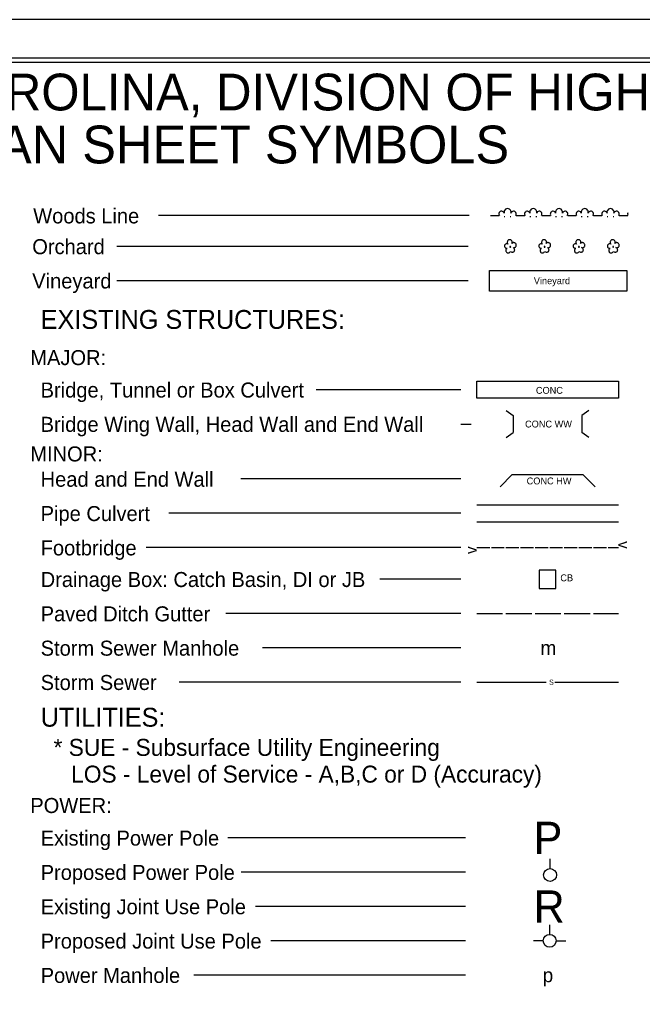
# Model space of a CAD drawing. Extents: x 2041685 to 2043369, y 619046 to 620146.
# Drawn here: x 2042608 to 2042971, y 619576 to 620146 of the extents above; entities that cross this region are included whole.
import ezdxf

# ---------------------------------------------------------------- set-up
doc = ezdxf.new("R2010")
doc.units = 0
for name, color, linetype in [('Sheet Cutting Line CELL', 7, 'Continuous'), ('Sheet Plot Border Inside CELL', 7, 'Continuous'), ('Sheet Plot Border Outside CELL', 7, 'Continuous'), ('Sheet Symbology CELL', 7, 'Continuous')]:
    doc.layers.add(name, color=color, linetype=linetype)

msp = doc.modelspace()

# ---------------------------------------------------------------- linework, layer by layer
at = {"layer": 'Sheet Cutting Line CELL'}
msp.add_line((2043369.03, 620145.62), (2041685.03, 620145.62), dxfattribs=at)
at = {"layer": 'Sheet Plot Border Inside CELL'}
msp.add_lwpolyline([(2041698.03, 619068.07), (2043364.53, 619068.07), (2043364.53, 620123.17), (2041698.03, 620123.17)], close=True, dxfattribs=at)
at = {"layer": 'Sheet Plot Border Outside CELL'}
msp.add_lwpolyline([(2041685.03, 619045.62), (2043369.03, 619045.62), (2043369.03, 620145.62), (2041685.03, 620145.62)], close=True, dxfattribs=at)
at = {"layer": 'Sheet Symbology CELL'}
for p, q in [((2042870.29, 620031.35), (2042689.16, 620031.35)), ((2042882.68, 620031.35), (2042887.68, 620031.35)), ((2042890.63, 620030.85), (2042891.13, 620030.85)), ((2042894.13, 620030.85), (2042894.63, 620030.85)), ((2042897.68, 620031.35), (2042902.68, 620031.35)), ((2042905.63, 620030.85), (2042906.13, 620030.85)), ((2042909.13, 620030.85), (2042909.63, 620030.85)), ((2042912.68, 620031.35), (2042917.68, 620031.35)), ((2042920.63, 620030.85), (2042921.13, 620030.85)), ((2042924.13, 620030.85), (2042924.63, 620030.85)), ((2042927.68, 620031.35), (2042932.68, 620031.35)), ((2042935.63, 620030.85), (2042936.13, 620030.85)), ((2042939.13, 620030.85), (2042939.63, 620030.85)), ((2042942.68, 620031.35), (2042947.68, 620031.35)), ((2042950.63, 620030.85), (2042951.13, 620030.85)), ((2042954.13, 620030.85), (2042954.63, 620030.85)), ((2042957.68, 620031.35), (2042962.68, 620031.35)), ((2042869.72, 620013.42), (2042664.79, 620013.42)), ((2042869.72, 619993.42), (2042664.79, 619993.42)), ((2042865.41, 619929.92), (2042780.98, 619929.92)), ((2042891.86, 619917.78), (2042895.96, 619914.92)), ((2042895.96, 619914.92), (2042895.96, 619904.92)), ((2042940.06, 619917.78), (2042935.96, 619914.92)), ((2042935.96, 619914.92), (2042935.96, 619904.92)), ((2042865.41, 619909.92), (2042871.4, 619909.92)), ((2042891.86, 619902.05), (2042895.96, 619904.92)), ((2042940.06, 619902.05), (2042935.96, 619904.92)), ((2042888.26, 619873.35), (2042895.33, 619880.42)), ((2042895.33, 619880.42), (2042936.58, 619880.42)), ((2042936.58, 619880.42), (2042943.66, 619873.35)), ((2042865.41, 619877.92), (2042737.11, 619877.92)), ((2042874.71, 619862.92), (2042957.21, 619862.92)), ((2042865.41, 619857.92), (2042695.22, 619857.92)), ((2042874.71, 619852.92), (2042957.21, 619852.92)), ((2042865.41, 619837.92), (2042681.93, 619837.92)), ((2042874.71, 619837.92), (2042882.21, 619837.92)), ((2042883.21, 619837.92), (2042890.71, 619837.92)), ((2042891.71, 619837.92), (2042899.21, 619837.92)), ((2042900.21, 619837.92), (2042907.71, 619837.92)), ((2042908.71, 619837.92), (2042916.21, 619837.92)), ((2042917.21, 619837.92), (2042924.71, 619837.92)), ((2042925.71, 619837.92), (2042933.21, 619837.92)), ((2042934.21, 619837.92), (2042941.71, 619837.92)), ((2042942.71, 619837.92), (2042950.21, 619837.92)), ((2042951.21, 619837.92), (2042957.21, 619837.92)), ((2042865.41, 619819.49), (2042818.21, 619819.49)), ((2042865.41, 619799.49), (2042728.46, 619799.49)), ((2042874.71, 619799.49), (2042889.71, 619799.49)), ((2042891.71, 619799.49), (2042906.71, 619799.49)), ((2042908.71, 619799.49), (2042923.71, 619799.49)), ((2042925.71, 619799.49), (2042940.71, 619799.49)), ((2042942.71, 619799.49), (2042957.21, 619799.49)), ((2042865.41, 619779.49), (2042749.73, 619779.49)), ((2042865.41, 619759.49), (2042701.21, 619759.49)), ((2042874.71, 619759.49), (2042915.23, 619759.49)), ((2042920.23, 619759.49), (2042957.21, 619759.49)), ((2042868.2, 619668.8), (2042729.5, 619668.8)), ((2042917.42, 619650.92), (2042917.42, 619656.54)), ((2042868.2, 619648.8), (2042737.28, 619648.8)), ((2042868.2, 619628.8), (2042745.68, 619628.8)), ((2042917.21, 619612.57), (2042917.21, 619618.19)), ((2042868.2, 619608.8), (2042754.68, 619608.8)), ((2042913.46, 619608.82), (2042907.83, 619608.82)), ((2042920.96, 619608.82), (2042926.58, 619608.82)), ((2042868.2, 619588.8), (2042709.7, 619588.8))]:
    msp.add_line(p, q, dxfattribs=at)
for points in [[(2043352.03, 620120.62), (2041852.03, 620120.62), (2041852.03, 619071.63), (2043352.03, 619071.63)], [(2042911.15, 619814.17), (2042920.76, 619814.17), (2042920.76, 619824.81), (2042911.15, 619824.81)]]:
    msp.add_lwpolyline(points, close=True, dxfattribs=at)
for points in [[(2042895.17, 620015.17), (2042895.32, 620015.47), (2042895.37, 620015.77), (2042895.32, 620016.07), (2042895.27, 620016.37), (2042895.12, 620016.62), (2042894.97, 620016.87), (2042894.72, 620017.07), (2042894.47, 620017.22), (2042894.12, 620017.32), (2042893.87, 620017.32), (2042893.57, 620017.27), (2042893.27, 620017.17), (2042893.02, 620017.02), (2042892.77, 620016.82), (2042892.62, 620016.52), (2042892.52, 620016.27), (2042892.47, 620015.97), (2042892.47, 620015.67), (2042892.52, 620015.37), (2042892.67, 620015.12), (2042892.87, 620014.82), (2042892.62, 620014.97), (2042892.32, 620015.02), (2042892.02, 620015.02), (2042891.77, 620014.92), (2042891.52, 620014.82), (2042891.27, 620014.62), (2042891.07, 620014.42), (2042890.92, 620014.17), (2042890.87, 620013.92), (2042890.82, 620013.57), (2042890.87, 620013.32), (2042890.97, 620013.07), (2042891.17, 620012.82), (2042891.32, 620012.62), (2042891.57, 620012.47), (2042891.87, 620012.32), (2042892.12, 620012.27), (2042892.42, 620012.27), (2042892.17, 620012.17), (2042891.92, 620011.97), (2042891.77, 620011.77), (2042891.67, 620011.47), (2042891.57, 620011.17), (2042891.57, 620010.92), (2042891.62, 620010.62), (2042891.77, 620010.37), (2042891.92, 620010.12), (2042892.12, 620009.92), (2042892.37, 620009.77), (2042892.62, 620009.67), (2042892.92, 620009.67), (2042893.22, 620009.67), (2042893.47, 620009.72), (2042893.72, 620009.92), (2042893.97, 620010.07), (2042894.22, 620010.52)], [(2042894.22, 620010.52), (2042894.82, 620010.17), (2042895.12, 620010.07), (2042895.42, 620010.02), (2042895.72, 620010.07), (2042895.97, 620010.17), (2042896.22, 620010.32), (2042896.47, 620010.52), (2042896.62, 620010.77), (2042896.72, 620011.02), (2042896.82, 620011.32), (2042896.77, 620011.62), (2042896.72, 620011.92), (2042896.52, 620012.22), (2042896.37, 620012.42), (2042896.12, 620012.57), (2042895.82, 620012.72), (2042896.12, 620012.67), (2042896.47, 620012.67), (2042896.72, 620012.77), (2042897.02, 620012.92), (2042897.27, 620013.07), (2042897.47, 620013.32), (2042897.62, 620013.62), (2042897.67, 620013.92), (2042897.72, 620014.22), (2042897.67, 620014.52), (2042897.57, 620014.82), (2042897.37, 620015.07), (2042897.12, 620015.32), (2042896.87, 620015.47), (2042896.57, 620015.57), (2042896.27, 620015.62), (2042895.97, 620015.62), (2042895.67, 620015.52), (2042895.42, 620015.37), (2042895.17, 620015.17)], [(2042915.17, 620015.17), (2042915.32, 620015.47), (2042915.37, 620015.77), (2042915.32, 620016.07), (2042915.27, 620016.37), (2042915.12, 620016.62), (2042914.97, 620016.87), (2042914.72, 620017.07), (2042914.47, 620017.22), (2042914.12, 620017.32), (2042913.87, 620017.32), (2042913.57, 620017.27), (2042913.27, 620017.17), (2042913.02, 620017.02), (2042912.77, 620016.82), (2042912.62, 620016.52), (2042912.52, 620016.27), (2042912.47, 620015.97), (2042912.47, 620015.67), (2042912.52, 620015.37), (2042912.67, 620015.12), (2042912.87, 620014.82), (2042912.62, 620014.97), (2042912.32, 620015.02), (2042912.02, 620015.02), (2042911.77, 620014.92), (2042911.52, 620014.82), (2042911.27, 620014.62), (2042911.07, 620014.42), (2042910.92, 620014.17), (2042910.87, 620013.92), (2042910.82, 620013.57), (2042910.87, 620013.32), (2042910.97, 620013.07), (2042911.17, 620012.82), (2042911.32, 620012.62), (2042911.57, 620012.47), (2042911.87, 620012.32), (2042912.12, 620012.27), (2042912.42, 620012.27), (2042912.17, 620012.17), (2042911.92, 620011.97), (2042911.77, 620011.77), (2042911.67, 620011.47), (2042911.57, 620011.17), (2042911.57, 620010.92), (2042911.62, 620010.62), (2042911.77, 620010.37), (2042911.92, 620010.12), (2042912.12, 620009.92), (2042912.37, 620009.77), (2042912.62, 620009.67), (2042912.92, 620009.67), (2042913.22, 620009.67), (2042913.47, 620009.72), (2042913.72, 620009.92), (2042913.97, 620010.07), (2042914.22, 620010.52)], [(2042914.22, 620010.52), (2042914.82, 620010.17), (2042915.12, 620010.07), (2042915.42, 620010.02), (2042915.72, 620010.07), (2042915.97, 620010.17), (2042916.22, 620010.32), (2042916.47, 620010.52), (2042916.62, 620010.77), (2042916.72, 620011.02), (2042916.82, 620011.32), (2042916.77, 620011.62), (2042916.72, 620011.92), (2042916.52, 620012.22), (2042916.37, 620012.42), (2042916.12, 620012.57), (2042915.82, 620012.72), (2042916.12, 620012.67), (2042916.47, 620012.67), (2042916.72, 620012.77), (2042917.02, 620012.92), (2042917.27, 620013.07), (2042917.47, 620013.32), (2042917.62, 620013.62), (2042917.67, 620013.92), (2042917.72, 620014.22), (2042917.67, 620014.52), (2042917.57, 620014.82), (2042917.37, 620015.07), (2042917.12, 620015.32), (2042916.87, 620015.47), (2042916.57, 620015.57), (2042916.27, 620015.62), (2042915.97, 620015.62), (2042915.67, 620015.52), (2042915.42, 620015.37), (2042915.17, 620015.17)], [(2042935.17, 620015.17), (2042935.32, 620015.47), (2042935.37, 620015.77), (2042935.32, 620016.07), (2042935.27, 620016.37), (2042935.12, 620016.62), (2042934.97, 620016.87), (2042934.72, 620017.07), (2042934.47, 620017.22), (2042934.12, 620017.32), (2042933.87, 620017.32), (2042933.57, 620017.27), (2042933.27, 620017.17), (2042933.02, 620017.02), (2042932.77, 620016.82), (2042932.62, 620016.52), (2042932.52, 620016.27), (2042932.47, 620015.97), (2042932.47, 620015.67), (2042932.52, 620015.37), (2042932.67, 620015.12), (2042932.87, 620014.82), (2042932.62, 620014.97), (2042932.32, 620015.02), (2042932.02, 620015.02), (2042931.77, 620014.92), (2042931.52, 620014.82), (2042931.27, 620014.62), (2042931.07, 620014.42), (2042930.92, 620014.17), (2042930.87, 620013.92), (2042930.82, 620013.57), (2042930.87, 620013.32), (2042930.97, 620013.07), (2042931.17, 620012.82), (2042931.32, 620012.62), (2042931.57, 620012.47), (2042931.87, 620012.32), (2042932.12, 620012.27), (2042932.42, 620012.27), (2042932.17, 620012.17), (2042931.92, 620011.97), (2042931.77, 620011.77), (2042931.67, 620011.47), (2042931.57, 620011.17), (2042931.57, 620010.92), (2042931.62, 620010.62), (2042931.77, 620010.37), (2042931.92, 620010.12), (2042932.12, 620009.92), (2042932.37, 620009.77), (2042932.62, 620009.67), (2042932.92, 620009.67), (2042933.22, 620009.67), (2042933.47, 620009.72), (2042933.72, 620009.92), (2042933.97, 620010.07), (2042934.22, 620010.52)], [(2042934.22, 620010.52), (2042934.82, 620010.17), (2042935.12, 620010.07), (2042935.42, 620010.02), (2042935.72, 620010.07), (2042935.97, 620010.17), (2042936.22, 620010.32), (2042936.47, 620010.52), (2042936.62, 620010.77), (2042936.72, 620011.02), (2042936.82, 620011.32), (2042936.77, 620011.62), (2042936.72, 620011.92), (2042936.52, 620012.22), (2042936.37, 620012.42), (2042936.12, 620012.57), (2042935.82, 620012.72), (2042936.12, 620012.67), (2042936.47, 620012.67), (2042936.72, 620012.77), (2042937.02, 620012.92), (2042937.27, 620013.07), (2042937.47, 620013.32), (2042937.62, 620013.62), (2042937.67, 620013.92), (2042937.72, 620014.22), (2042937.67, 620014.52), (2042937.57, 620014.82), (2042937.37, 620015.07), (2042937.12, 620015.32), (2042936.87, 620015.47), (2042936.57, 620015.57), (2042936.27, 620015.62), (2042935.97, 620015.62), (2042935.67, 620015.52), (2042935.42, 620015.37), (2042935.17, 620015.17)], [(2042955.17, 620015.17), (2042955.32, 620015.47), (2042955.37, 620015.77), (2042955.32, 620016.07), (2042955.27, 620016.37), (2042955.12, 620016.62), (2042954.97, 620016.87), (2042954.72, 620017.07), (2042954.47, 620017.22), (2042954.12, 620017.32), (2042953.87, 620017.32), (2042953.57, 620017.27), (2042953.27, 620017.17), (2042953.02, 620017.02), (2042952.77, 620016.82), (2042952.62, 620016.52), (2042952.52, 620016.27), (2042952.47, 620015.97), (2042952.47, 620015.67), (2042952.52, 620015.37), (2042952.67, 620015.12), (2042952.87, 620014.82), (2042952.62, 620014.97), (2042952.32, 620015.02), (2042952.02, 620015.02), (2042951.77, 620014.92), (2042951.52, 620014.82), (2042951.27, 620014.62), (2042951.07, 620014.42), (2042950.92, 620014.17), (2042950.87, 620013.92), (2042950.82, 620013.57), (2042950.87, 620013.32), (2042950.97, 620013.07), (2042951.17, 620012.82), (2042951.32, 620012.62), (2042951.57, 620012.47), (2042951.87, 620012.32), (2042952.12, 620012.27), (2042952.42, 620012.27), (2042952.17, 620012.17), (2042951.92, 620011.97), (2042951.77, 620011.77), (2042951.67, 620011.47), (2042951.57, 620011.17), (2042951.57, 620010.92), (2042951.62, 620010.62), (2042951.77, 620010.37), (2042951.92, 620010.12), (2042952.12, 620009.92), (2042952.37, 620009.77), (2042952.62, 620009.67), (2042952.92, 620009.67), (2042953.22, 620009.67), (2042953.47, 620009.72), (2042953.72, 620009.92), (2042953.97, 620010.07), (2042954.22, 620010.52)], [(2042954.22, 620010.52), (2042954.82, 620010.17), (2042955.12, 620010.07), (2042955.42, 620010.02), (2042955.72, 620010.07), (2042955.97, 620010.17), (2042956.22, 620010.32), (2042956.47, 620010.52), (2042956.62, 620010.77), (2042956.72, 620011.02), (2042956.82, 620011.32), (2042956.77, 620011.62), (2042956.72, 620011.92), (2042956.52, 620012.22), (2042956.37, 620012.42), (2042956.12, 620012.57), (2042955.82, 620012.72), (2042956.12, 620012.67), (2042956.47, 620012.67), (2042956.72, 620012.77), (2042957.02, 620012.92), (2042957.27, 620013.07), (2042957.47, 620013.32), (2042957.62, 620013.62), (2042957.67, 620013.92), (2042957.72, 620014.22), (2042957.67, 620014.52), (2042957.57, 620014.82), (2042957.37, 620015.07), (2042957.12, 620015.32), (2042956.87, 620015.47), (2042956.57, 620015.57), (2042956.27, 620015.62), (2042955.97, 620015.62), (2042955.67, 620015.52), (2042955.42, 620015.37), (2042955.17, 620015.17)], [(2042894.32, 620013.42), (2042894.17, 620013.42), (2042894.07, 620013.37), (2042893.97, 620013.32), (2042893.97, 620013.17), (2042893.97, 620013.07), (2042894.07, 620012.97), (2042894.22, 620012.97), (2042894.32, 620012.97), (2042894.42, 620013.07), (2042894.47, 620013.22), (2042894.42, 620013.32), (2042894.32, 620013.42)], [(2042914.32, 620013.42), (2042914.17, 620013.42), (2042914.07, 620013.37), (2042913.97, 620013.32), (2042913.97, 620013.17), (2042913.97, 620013.07), (2042914.07, 620012.97), (2042914.22, 620012.97), (2042914.32, 620012.97), (2042914.42, 620013.07), (2042914.47, 620013.22), (2042914.42, 620013.32), (2042914.32, 620013.42)], [(2042934.32, 620013.42), (2042934.17, 620013.42), (2042934.07, 620013.37), (2042933.97, 620013.32), (2042933.97, 620013.17), (2042933.97, 620013.07), (2042934.07, 620012.97), (2042934.22, 620012.97), (2042934.32, 620012.97), (2042934.42, 620013.07), (2042934.47, 620013.22), (2042934.42, 620013.32), (2042934.32, 620013.42)], [(2042954.32, 620013.42), (2042954.17, 620013.42), (2042954.07, 620013.37), (2042953.97, 620013.32), (2042953.97, 620013.17), (2042953.97, 620013.07), (2042954.07, 620012.97), (2042954.22, 620012.97), (2042954.32, 620012.97), (2042954.42, 620013.07), (2042954.47, 620013.22), (2042954.42, 620013.32), (2042954.32, 620013.42)], [(2042882.12, 619999.42), (2042962.12, 619999.42), (2042962.12, 619987.42), (2042882.12, 619987.42), (2042882.12, 619999.42)], [(2042874.71, 619934.92), (2042957.21, 619934.92), (2042957.21, 619924.92), (2042874.71, 619924.92), (2042874.71, 619934.92)]]:
    msp.add_lwpolyline(points, dxfattribs=at)
for centre in [(2042917.42, 619647.17), (2042917.21, 619608.8)]:
    msp.add_circle(centre, 3.75, dxfattribs=at)
for centre, radius, start, end in [((2042889.13, 620032.36), 1.58, 18.435, 219.2315), ((2042892.63, 620033.36), 2.06, 345.9638, 194.0362), ((2042896.13, 620032.36), 1.58, 320.7685, 161.5651), ((2042904.13, 620032.36), 1.58, 18.435, 219.2315), ((2042907.63, 620033.36), 2.06, 345.9638, 194.0362), ((2042911.13, 620032.36), 1.58, 320.7685, 161.5651), ((2042919.13, 620032.36), 1.58, 18.435, 219.2315), ((2042922.63, 620033.36), 2.06, 345.9638, 194.0362), ((2042926.13, 620032.36), 1.58, 320.7685, 161.5651), ((2042934.13, 620032.36), 1.58, 18.435, 219.2315), ((2042937.63, 620033.36), 2.06, 345.9638, 194.0362), ((2042941.13, 620032.36), 1.58, 320.7685, 161.5651), ((2042949.13, 620032.36), 1.58, 18.435, 219.2315), ((2042952.63, 620033.36), 2.06, 345.9638, 194.0362), ((2042956.13, 620032.36), 1.58, 320.7685, 161.5651), ((2042964.13, 620032.36), 1.58, 156.251, 203.749)]:
    msp.add_arc(centre, radius, start, end, dxfattribs=at)

# ---------------------------------------------------------------- texts
for s, height, p in [('STATE OF NORTH CAROLINA, DIVISION OF HIGHWAYS', 21.419, (2042302.59, 620092.66)), ('CONVENTIONAL  PLAN SHEET SYMBOLS', 22.0323, (2042310.72, 620061.78)), ('Woods Line', 8.75, (2042616.13, 620026.82)), ('Orchard', 8.75, (2042615.56, 620008.9)), ('Vineyard', 8.75, (2042615.56, 619988.9)), ('EXISTING STRUCTURES:', 11, (2042620.45, 619965.37)), ('MAJOR:', 8.75, (2042614.42, 619944.25)), ('Bridge, Tunnel or Box Culvert', 8.75, (2042620.45, 619925.37)), ('CONC', 4, (2042909.15, 619927.55)), ('Bridge Wing Wall, Head Wall and End Wall', 8.75, (2042620.45, 619905.37)), ('MINOR:', 8.75, (2042614.42, 619888.13)), ('Head and End Wall', 8.75, (2042620.45, 619873.37)), ('Pipe Culvert', 8.75, (2042620.45, 619853.38)), ('Footbridge', 8.75, (2042620.46, 619833.38)), ('Drainage Box: Catch Basin, DI or JB', 8.75, (2042620.46, 619814.95)), ('Paved Ditch Gutter', 8.75, (2042620.46, 619794.94)), ('Storm Sewer Manhole', 8.75, (2042620.46, 619774.94)), ('m', 8.25, (2042911.83, 619775.36)), ('Storm Sewer', 8.75, (2042620.46, 619754.94)), ('S', 3, (2042916.83, 619757.99)), ('UTILITIES:', 11, (2042620.45, 619733.57)), ('POWER:', 8.75, (2042614.42, 619683.27)), ('Existing Power Pole', 8.75, (2042620.46, 619664.27)), ('P', 18.75, (2042907.83, 619659.43)), ('Proposed Power Pole', 8.75, (2042620.46, 619644.27)), ('Existing Joint Use Pole', 8.75, (2042620.46, 619624.28)), ('R', 18.75, (2042907.83, 619619.43)), ('Proposed Joint Use Pole', 8.75, (2042620.47, 619604.27)), ('Power Manhole', 8.75, (2042620.47, 619584.27)), ('p', 8.25, (2042913.08, 619584.68))]:
    msp.add_text(s, height=height, dxfattribs=at).set_placement(p)
for s, height, rotation, p in [('Vineyard', 4, 0, (2042907.94, 619991.42)), ('CONC WW', 4, 0, (2042902.83, 619907.92)), ('CONC HW', 4, 360, (2042903.76, 619874.76)), ('v', 6.6, 89.7591, (2042874.7, 619834.18)), ('v', 6.6, 270.2409, (2042957.2, 619841.66)), ('CB', 4, 360, (2042923.4, 619818.31)), ('* SUE - Subsurface Utility Engineering', 9.9, 360, (2042627.98, 619716.55)), ('LOS - Level of Service - A,B,C or D (Accuracy) ', 9.9, 360, (2042638.25, 619700.98))]:
    msp.add_text(s, height=height, rotation=rotation, dxfattribs=at).set_placement(p)

doc.saveas('drawing.dxf')
